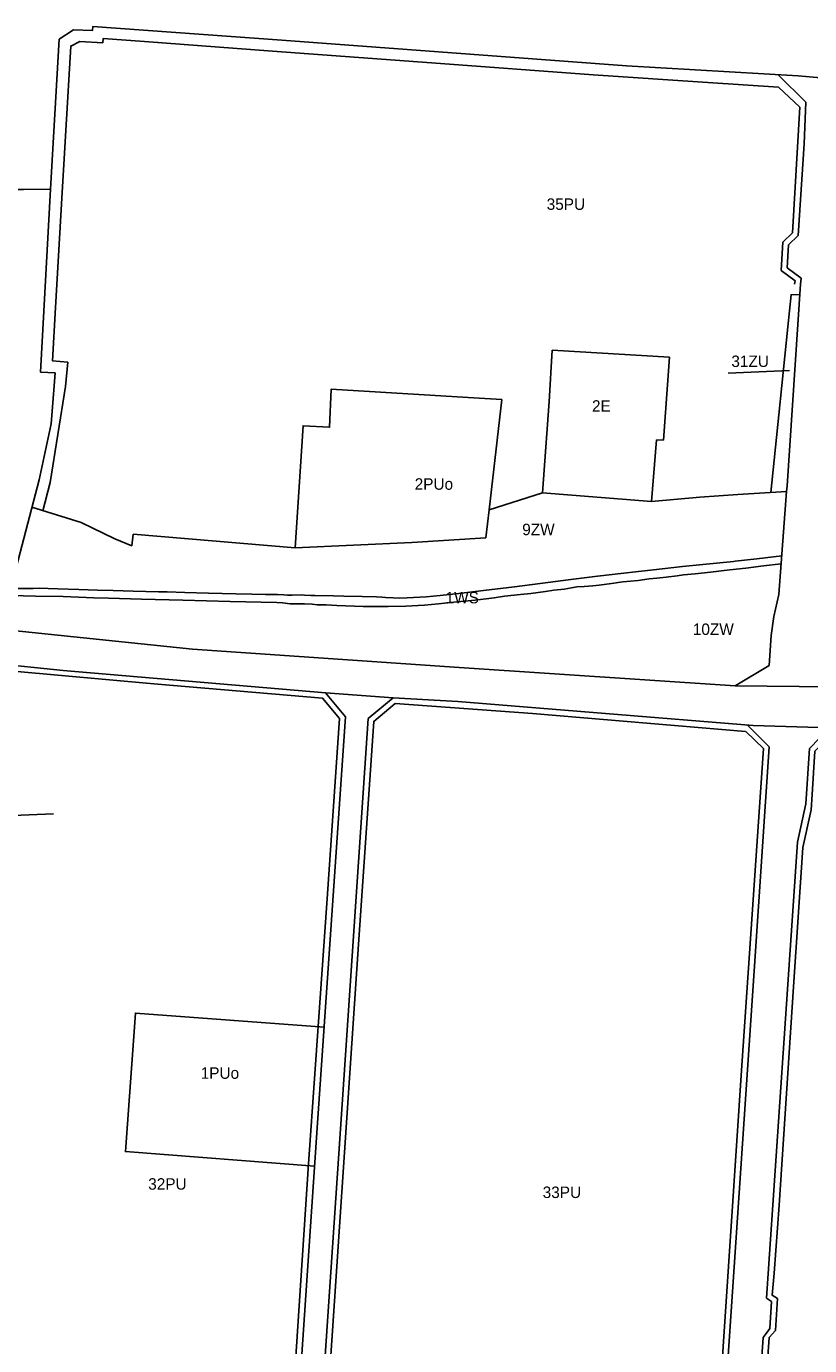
# Model space of a CAD drawing. Extents: x 7428203 to 7432868, y 5542672 to 5545406.
# Drawn here: x 7431420 to 7432101, y 5543958 to 5545107 of the extents above; entities that cross this region are included whole.
import ezdxf

# ---------------------------------------------------------------- set-up
doc = ezdxf.new("R2010")
doc.units = 0
for name, color, linetype in [('granica_planu', 7, 'Continuous'), ('linie_rozgraniczajace', 7, 'Continuous'), ('linie_zabudowy_nieprzekraczalne', 7, 'Continuous'), ('oznaczenia_przeznaczen', 7, 'Continuous')]:
    doc.layers.add(name, color=color, linetype=linetype)

msp = doc.modelspace()

# ---------------------------------------------------------------- linework, layer by layer
at = {"layer": 'granica_planu'}
msp.add_lwpolyline([(7431383.69, 5544964.48), (7431440.72, 5544964.99), (7431448.16, 5545095.63), (7431460.67, 5545103.92), (7431477.2, 5545103.11), (7431477.58, 5545106.79), (7431642.09, 5545094.68), (7431942.21, 5545072.47), (7432091.43, 5545063.63), (7432213.18, 5545053.04)], dxfattribs=at)
at = {"layer": 'linie_rozgraniczajace'}
for p, q in [((7431448.16, 5545095.63), (7431460.67, 5545103.92)), ((7431460.67, 5545103.92), (7431477.2, 5545103.11)), ((7431477.2, 5545103.11), (7431477.58, 5545106.79)), ((7431477.58, 5545106.79), (7431642.09, 5545094.68)), ((7431440.72, 5544964.99), (7431448.16, 5545095.63)), ((7431642.09, 5545094.68), (7431942.21, 5545072.47)), ((7431942.21, 5545072.47), (7432091.43, 5545063.63)), ((7432073.97, 5545064.66), (7432098.18, 5545040.84)), ((7432091.43, 5545063.63), (7432213.18, 5545053.04)), ((7432098.18, 5545040.84), (7432096.88, 5545004.37)), ((7432096.88, 5545004.37), (7432091.53, 5544924.77)), ((7431383.69, 5544964.48), (7431440.72, 5544964.99)), ((7431431.99, 5544805.68), (7431440.72, 5544964.99)), ((7432091.53, 5544924.77), (7432082.98, 5544916.57)), ((7432082.98, 5544916.57), (7432081.98, 5544896.59)), ((7432081.98, 5544896.59), (7432094.02, 5544887.55)), ((7432094.02, 5544887.55), (7432093.66, 5544882.24)), ((7432093.66, 5544882.24), (7432081.83, 5544706.66)), ((7431877.4, 5544824.92), (7431874.67, 5544780.04)), ((7431979.45, 5544818.71), (7431877.4, 5544824.92)), ((7431974.29, 5544746.38), (7431979.45, 5544818.71)), ((7431444.83, 5544804.91), (7431431.99, 5544805.68)), ((7431443.89, 5544793.65), (7431444.83, 5544804.91)), ((7431963.74, 5544693.09), (7431968.32, 5544746.83)), ((7431968.32, 5544746.83), (7431974.29, 5544746.38)), ((7432081.83, 5544706.66), (7432081.47, 5544701.72)), ((7431822.53, 5544685.71), (7431868.88, 5544700.51)), ((7432005.8, 5544696.89), (7431963.74, 5544693.09)), ((7432038.88, 5544699.01), (7432005.8, 5544696.89)), ((7432081.47, 5544701.72), (7432038.88, 5544699.01)), ((7431819.72, 5544661.32), (7431822.53, 5544685.71)), ((7431653.64, 5544652.78), (7431512.78, 5544664.42)), ((7431755.36, 5544657.37), (7431653.64, 5544652.78)), ((7431819.72, 5544661.32), (7431755.36, 5544657.37)), ((7432036.81, 5544532.49), (7432120.16, 5544531.65)), ((7431680.1, 5544526.46), (7431738.89, 5544522.08)), ((7431738.89, 5544522.08), (7431717.21, 5544503.92)), ((7431795.36, 5544518.69), (7431738.89, 5544522.08)), ((7432052.47, 5544497.76), (7431795.36, 5544518.69)), ((7431717.21, 5544503.92), (7431696.5, 5544197.97)), ((7432066.32, 5544479.29), (7432047.48, 5544498.17)), ((7432052.47, 5544497.76), (7432118.72, 5544495.85)), ((7432118.72, 5544495.85), (7432101.27, 5544477.81)), ((7432053.71, 5544292.64), (7432066.32, 5544479.29)), ((7432101.27, 5544477.81), (7432098.2, 5544429.77)), ((7432098.2, 5544429.77), (7432090.81, 5544396.17)), ((7432090.81, 5544396.17), (7432064.08, 5543999.05)), ((7432024.19, 5543851.74), (7432053.71, 5544292.64)), ((7431696.5, 5544197.97), (7431674.68, 5543875.42)), ((7432064.08, 5543999.05), (7432068.42, 5543996.12)), ((7432068.42, 5543996.12), (7432066.8, 5543972.69)), ((7432063.53, 5543968.27), (7432061.05, 5543964.92)), ((7432066.8, 5543972.69), (7432063.53, 5543968.27)), ((7432061.05, 5543964.92), (7432053.02, 5543849.76))]:
    msp.add_line(p, q, dxfattribs=at)
for points in [[(7432067.77, 5544700.85), (7432074.7, 5544768.56), (7432082.54, 5544845.22), (7432085.39, 5544873.06), (7432093.06, 5544873.26)], [(7431443.89, 5544793.65), (7431441.13, 5544760.73), (7431430.72, 5544711.87), (7431401.06, 5544597.34), (7431397.08, 5544588.16), (7431402.52, 5544581.13), (7431564.3, 5544564.44), (7431796.47, 5544548.52), (7432036.81, 5544532.49), (7432066.29, 5544550.26), (7432068.15, 5544576.37), (7432070.42, 5544592.86), (7432074.81, 5544612.13), (7432081.47, 5544701.72)], [(7431653.64, 5544652.78), (7431660.62, 5544758.91), (7431683.68, 5544757.63), (7431685.05, 5544790.85), (7431813.83, 5544782.97), (7431833.42, 5544781.71), (7431822.53, 5544685.71)], [(7431963.74, 5544693.09), (7431868.88, 5544700.51), (7431874.67, 5544780.04)], [(7431512.78, 5544664.42), (7431511.41, 5544654.52), (7431496.68, 5544660.48), (7431467.47, 5544674.8), (7431424.58, 5544688.15)], [(7432077.31, 5544645.68), (7432055.52, 5544643.12), (7432036.72, 5544640.89), (7432035.25, 5544640.85), (7432008.49, 5544638.18), (7431990.82, 5544636.39), (7431965.6, 5544633.6), (7431949.95, 5544631.86), (7431939.71, 5544630.6), (7431916.88, 5544627.94), (7431893.55, 5544624.97), (7431866.9, 5544621.7), (7431844.45, 5544618.74), (7431817.71, 5544615.44), (7431796.08, 5544612.77), (7431779.85, 5544611.02), (7431767.61, 5544610.02), (7431751.1, 5544608.96), (7431744.27, 5544608.83), (7431738.88, 5544608.98), (7431732.35, 5544609.49), (7431729.14, 5544609.73), (7431724.51, 5544609.92), (7431712, 5544610.25), (7431696.15, 5544610.68), (7431687.09, 5544610.89), (7431670.75, 5544611.14), (7431667.39, 5544611.2), (7431661.76, 5544611.5), (7431659.44, 5544611.58), (7431651.16, 5544611.54), (7431647.09, 5544611.5), (7431643.7, 5544611.61), (7431638.42, 5544611.92), (7431627.8, 5544612.06), (7431616.06, 5544612.33), (7431602.05, 5544612.66), (7431578.24, 5544613.16), (7431557.74, 5544613.77), (7431542.13, 5544614.35), (7431534.59, 5544614.42), (7431512.79, 5544614.96), (7431495.16, 5544615.36), (7431481.57, 5544615.73), (7431465.27, 5544616.29), (7431447.19, 5544617.05), (7431438.58, 5544617.34), (7431431, 5544617.43), (7431425.71, 5544617.19), (7431419.97, 5544617.18), (7431412.41, 5544617.3)], [(7431406.67, 5544611.13), (7431427.51, 5544610.68), (7431451.7, 5544610.12), (7431478.33, 5544609.11), (7431491.15, 5544608.89), (7431519.89, 5544607.91), (7431555.77, 5544607.04), (7431597.02, 5544605.96), (7431637.78, 5544604.93), (7431642.69, 5544604.68), (7431649.18, 5544604), (7431661.77, 5544603.72), (7431668.39, 5544603.49), (7431672.89, 5544602.92), (7431680.58, 5544603.09), (7431689.81, 5544602.42), (7431712.84, 5544601.46), (7431734.66, 5544601.45), (7431749.86, 5544601.82), (7431766.28, 5544602.79), (7431778.36, 5544603.82), (7431791.8, 5544605.31), (7431810.47, 5544607.02), (7431826.94, 5544609.23), (7431835.81, 5544610.48), (7431849.72, 5544612.04), (7431858.68, 5544612.9), (7431871.63, 5544614.72), (7431878.95, 5544615.67), (7431887.81, 5544616.57), (7431894.13, 5544617.72), (7431898.76, 5544618.61), (7431905.36, 5544619.03), (7431912.74, 5544619.47), (7431918.36, 5544620.2), (7431929.14, 5544621.53), (7431939.03, 5544622.88), (7431952.2, 5544624.11), (7431961.79, 5544625.54), (7431968.42, 5544626.21), (7431976.75, 5544626.95), (7431986.28, 5544628.38), (7431991.77, 5544629), (7432001.76, 5544629.85), (7432015.06, 5544631.49), (7432032.13, 5544633.47), (7432045.91, 5544635.07), (7432061.3, 5544636.84), (7432076.78, 5544638.57)], [(7431654.46, 5543877.07), (7431672.85, 5544147.41), (7431697.38, 5544505.35), (7431680.1, 5544526.46), (7431451.66, 5544545.79), (7431389.69, 5544552.15)], [(7431670.59, 5544114.16), (7431505.87, 5544126.82), (7431514.54, 5544247.4), (7431678.86, 5544235.13)]]:
    msp.add_lwpolyline(points, dxfattribs=at)
at = {"layer": 'linie_zabudowy_nieprzekraczalne'}
for p, q in [((7432071.81, 5543971.05), (7432066.4, 5543964.87)), ((7432066.4, 5543964.87), (7432041.61, 5543620.95))]:
    msp.add_line(p, q, dxfattribs=at)
for points in [[(7431633.99, 5545085.14), (7431522.57, 5545093.55), (7431486.53, 5545096.1), (7431486.15, 5545092.48), (7431466.33, 5545093.61), (7431458.3, 5545089.6), (7431450.73, 5544962.18), (7431445.07, 5544862.05)], [(7432074.43, 5545053.71), (7432013.01, 5545057.82), (7431913.11, 5545064.64), (7431772.36, 5545075.01), (7431633.99, 5545085.14)], [(7432088.39, 5544882.37), (7432088.85, 5544885.18), (7432076.86, 5544894.19), (7432078.09, 5544918.8), (7432086.67, 5544927.04), (7432092.92, 5545036.39), (7432074.43, 5545053.71)], [(7431445.07, 5544862.05), (7431442.49, 5544815.46), (7431455.65, 5544814.28), (7431453.75, 5544793.18)], [(7431453.75, 5544793.18), (7431440.46, 5544709.58), (7431434.06, 5544684.87)], [(7431649.47, 5543877.41), (7431655.88, 5543974.89), (7431665.17, 5544116.21), (7431681.81, 5544351.27), (7431692.14, 5544503.86), (7431677.57, 5544521.65), (7431530.62, 5544534.23), (7431408.5, 5544545.23)], [(7432045.54, 5544492.68), (7431860.4, 5544508.47), (7431740.58, 5544516.97), (7431722.06, 5544501.46), (7431708.61, 5544303.22), (7431682.26, 5543914.58), (7431678.23, 5543855.15), (7431673.15, 5543780.29), (7431671.48, 5543755.53), (7431672.12, 5543735.74), (7431673.66, 5543716.32), (7431676.18, 5543696.55), (7431679.04, 5543674.23), (7431683.33, 5543670.2), (7431727.11, 5543673.28), (7431761.22, 5543672.6), (7431783.87, 5543669.93), (7431896.16, 5543650.19), (7431993.34, 5543628.23)], [(7431992.94, 5543628.74), (7431992.94, 5543628.74), (7432003.08, 5543637.39), (7432005.96, 5543673.78), (7432013.24, 5543765.46), (7432019.21, 5543852.08), (7432042.45, 5544201.74), (7432061.21, 5544477.78), (7432045.87, 5544492.57)], [(7432388.79, 5544473.79), (7432120.65, 5544490.65), (7432106.14, 5544475.66), (7432103.72, 5544437.8), (7432102.87, 5544424.52), (7432095.51, 5544391.55), (7432087.54, 5544270.16), (7432075.05, 5544080.02), (7432070.49, 5544020.98), (7432069, 5544001.68), (7432073.61, 5543998.74), (7432071.81, 5543971.05)]]:
    msp.add_lwpolyline(points, dxfattribs=at)
at = {"layer": 'oznaczenia_przeznaczen'}
for p, q in [((7432084.07, 5544807), (7432030.6, 5544804.83)), ((7431443.25, 5544421.06), (7431376.15, 5544418.34))]:
    msp.add_line(p, q, dxfattribs=at)

# ---------------------------------------------------------------- texts
for s, p in [('35PU', (7431872.6028, 5544946.98)), ('31ZU', (7432033.3628, 5544810.13)), ('2E', (7431912.0212, 5544771.17)), ('2PUo', (7431757.6877, 5544703.23)), ('9ZW', (7431851.3064, 5544663.62)), ('1WS', (7431784.6159, 5544604.31)), ('10ZW', (7431999.8233, 5544576.74)), ('1PUo', (7431571.4277, 5544190.19)), ('32PU', (7431525.7428, 5544093.62)), ('33PU', (7431869.1228, 5544086.36))]:
    msp.add_text(s, height=10, dxfattribs=at).set_placement(p)

doc.saveas('drawing.dxf')
